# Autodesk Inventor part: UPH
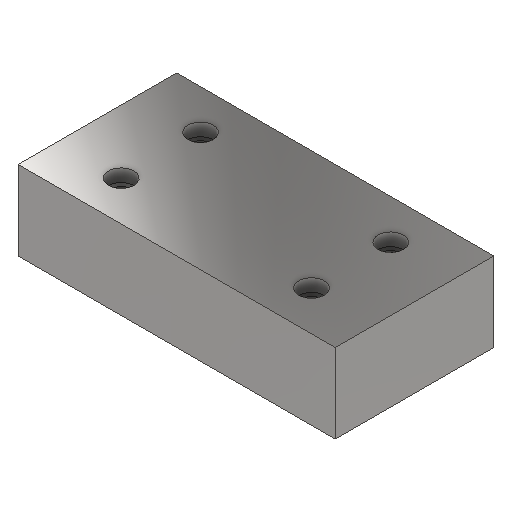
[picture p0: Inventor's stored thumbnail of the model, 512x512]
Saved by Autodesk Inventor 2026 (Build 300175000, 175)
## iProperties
Created: 2022-01
Part Number: UPH
Material: Steel, Mild
Document SubType Name: Modeling
Designer: Lars Bertram Pedersen
Density: 7.85 g/cm^3
Appearance: Semi-Polished
Mass: 353.966 g
Surface Area: 128.037 cm^2
Volume: 45.0913 cm^3
Author: Lars Bertram Pedersen
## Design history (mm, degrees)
sketch "Sketch2"
  geometry: L1 (-50, -25)-(50, -25); L2 (50, -25)-(50, 25); L3 (50, 25)-(-50, 25); L4 (-50, 25)-(-50, -25); L5 (-50, -25)-(50, 25); L6 (50, -25)-(-50, 25); 1 further point
  constraints: 12 end point, 2 midpoint, 2 parallel, 1 horizontal, 1 perpendicular
  dimensions: "d0" = 100 distance of L3.end L2.end; "d1" = 50 distance of L2.end L1.end
extrude "Extrusion2" new body sketch "Sketch2" distance "d2" = 25; taper "d3" = 0 deg
sketch "Sketch3"
  geometry: L1 (-50, -25)-(-50, 25) reference; L2 (50, -25)-(-50, -25) reference; 2 further points
  dimensions: "d12" = 20 distance from line of point (-30, -12.5) L1; "d13" = 12.5 distance from line of point (-30, -12.5) L2
hole "Hole1" sketch "Sketch3" diameter "d14" = 5; stored, may be unused: countersink angle "d18" = 90 deg, drill point angle "d20" = 118 deg; dims "d15" = 6, "d16" = 8, "d17" = 4, "d19" = 15
pattern_linear "Rectangular Pattern1" dims "d35" = 25
body "Solid2"
